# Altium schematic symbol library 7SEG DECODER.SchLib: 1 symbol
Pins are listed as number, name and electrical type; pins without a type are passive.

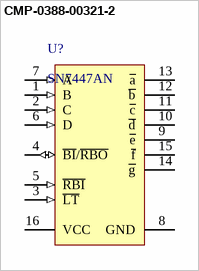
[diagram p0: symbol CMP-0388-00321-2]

## CMP-0388-00321-2
designator U?, comment SN7447AN
BCD-to-7-Segment Decoder / Driver, 4.75 to 5.25 V, 0 to 70 degC, 16-pin DIP (N16), Pb-Free (RoHS); Manufacturer: Texas Instruments; SubFamily: Discrete Segment LED Driver; Vin(Max)(V): 5.25; Vin(Min)(V): 4.75
footprint N0016A (DIP, 16-Leads, Body 19.7x6.6mm, Pitch 2.54mm)
pins: 1 B (in), 2 C (in), 3 ~{LT} (in), 4 ~{BI}/~{RBO} (io), 5 ~{RBI} (in), 6 D (in), 7 A (in), 8 GND (power), 9 ~{e} (oc), 10 ~{d} (oc), 11 ~{c} (oc), 12 ~{b} (oc), 13 ~{a} (oc), 14 ~{g} (oc), 15 ~{f} (oc), 16 VCC (power)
